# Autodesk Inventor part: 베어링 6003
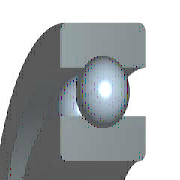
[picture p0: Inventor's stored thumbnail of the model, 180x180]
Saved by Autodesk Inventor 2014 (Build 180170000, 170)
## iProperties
Created: 2012-02
Part Number: 베어링 6003
Material: 강철, 연강
Description: 깊은 그루브 볼 베어링
Document SubType Name: Modeling
Standard: KS B 2023
Designer: mduedu
Standards Organization: KS
Language: ko-KR
Size Designation: 6003 - 17 x 35 x 10
Categories: <MemberInstance><Categories><Category DisplayName="샤프트 부품" InternalName="7f7aeb1f-a693-4053-b835-cee3144e0d98" Mnemonic="SHFT"><Category DisplayName="베어링" Inter
Density: 1 g/cm^3
Appearance: 노란색
IsCustomPart: 1
Author: mduedu
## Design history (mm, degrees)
sketch "스케치" dims "d0" = 4.68 (= -0.26 x WD + 0.26 x BD)
  geometry: L1 (2.66, 13)-(7.34, 13); L2 (5, 13)-(5, 10.66); L3 (5, 13)-(5, 15.34); L4 (3.261, 11.434)-(0, 11.434); L5 (0, 8.5)-(10, 8.5); L6 (3.261, 14.566)-(0, 14.566); L7 (0, 17.5)-(10, 17.5); L8 (10, 8.5)-(10, 11.434); L9 (6.739, 11.434)-(10, 11.434); L10 (6.739, 14.566)-(10, 14.566); L11 (10, 17.5)-(10, 14.566); L12 (-1.4, 0)-(8.4, 0) reference; L13 (0, -0.3)-(0, 5.3) reference
  constraints: 22 end point, 4 point on line, 2 collinear, 2 perpendicular, 2 symmetric about line, 1 midpoint, 1 parallel, 14 other
  dimensions: "d9" = 17 diameter of L5 L12 (= WD); "d11" = 35 diameter of L7 L12 (= BD); "d12" = 10 distance between parallel lines of L8 L13 (= KB); "d13" = 22.868 diameter of L9 L12 (= 0.326 x BD + 0.674 x WD)
revolve "본체" stored, may be unused: angle "d6" = 90 deg
revolve "볼" stored, may be unused: angle "d7" = 90 deg
pattern_circular "IDS_ARRAYBALL[SIMPL:T]" dims angle "d3" = 360 deg
body "Solid1"
fillet "모깎기1" dims "d1" = 0.3 (= KRS)
other parameters: "WD" = 17 [user parameter; used in 5 equation terms], "BD" = 35 [user parameter; used in 5 equation terms], "KB" = 10 [user parameter; used in 1 equation term], "KRS" = 0.3 [user parameter; used in 1 equation term], "d4" = 0, "d5" = 0, "d8" = 0, "d14" = 0, "d15" = 0, "BBA" = 0 [user parameter], "BC0" = 3250000 [user parameter], "BC" = 6050000 [user parameter], "BR" = 17.5 (= 0.5 x BD) [user parameter], "WR" = 8.5 (= 0.5 x WD) [user parameter]
